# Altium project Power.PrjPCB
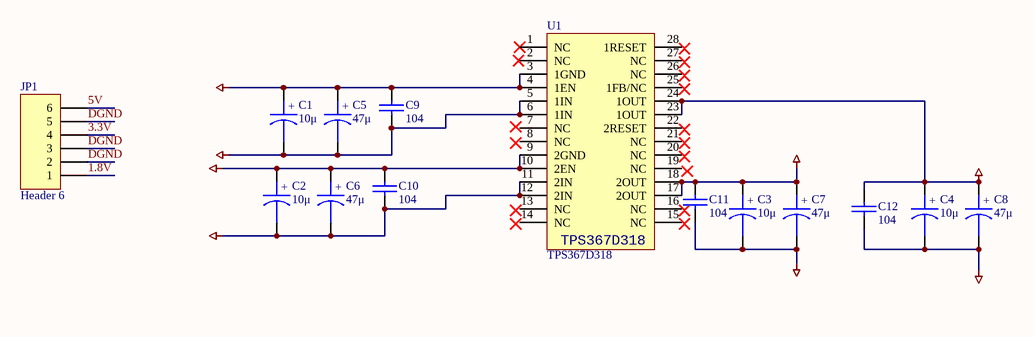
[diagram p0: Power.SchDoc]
1 sheet, 14 parts. Net scope: global (net labels, ports and power ports of the same name join across sheets).
Board file: Power.PcbDoc

## Sheet Power.SchDoc
size A4

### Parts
C1  10μ  [RB5-10.5]
C2  10μ  [RB5-10.5]
C3  10μ  [RB5-10.5]
C4  10μ  [RB5-10.5]
C5  47μ  [RB5-10.5]
C6  47μ  [RB5-10.5]
C7  47μ  [RB5-10.5]
C8  47μ  [RB5-10.5]
C9  104  [CC2012-0805]
C10  104  [CC2012-0805]
C11  104  [CC2012-0805]
C12  104  [CC2012-0805]
JP1  Header 6  [HDR1X6]
U1  TPS367D318  [TSSO10X6-G28]

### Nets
1.8V: C4.1 C8.1 C12.1 JP1.1 U1.23(1OUT) U1.24(1OUT)
3.3V: C3.1 C7.1 C11.1 JP1.4 U1.17(2OUT) U1.18(2OUT)
5V: C1.2 C2.2 C5.2 C6.2 C9.2 C10.2 JP1.6 U1.5(1IN) U1.6(1IN) U1.11(2IN) U1.12(2IN)
DGND: C1.1 C2.1 C3.2 C4.2 C5.1 C6.1 C7.2 C8.2 C9.1 C10.1 C11.2 C12.2 JP1.2 JP1.3 JP1.5 U1.3(1GND) U1.4(1EN) U1.9(2GND) U1.10(2EN)

Not connected (* = marked no-connect by the designer): U1 1(NC)* 2(NC) 7(NC) 8(NC) 13(NC) 14(NC) 15(NC) 16(NC) 19(NC) 20(NC) 21(NC) 22(2RESET) 25(1FB/NC) 26(NC) 27(NC) 28(1RESET)

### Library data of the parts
C1-C8 = CAPACITOR POL: Capacitor
C9-C12 = CAP: Capacitor
JP1 = Header 6: Header, 6-Pin; Manufacturer: Generic Components; Class I: Connector
U1 = TPS367D318: POWRE; Manufacturer: Texas Instruments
